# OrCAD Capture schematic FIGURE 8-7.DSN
size A
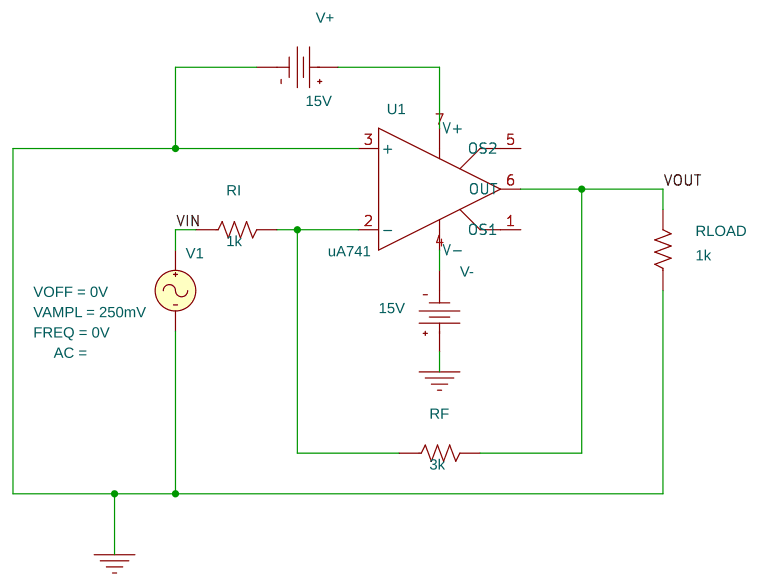
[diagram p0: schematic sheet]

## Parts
RF  3k  [AX/RC05]
RI  1k  [AX/RC05]
RLOAD  1k  [AX/RC05]
U1  uA741  [DIP.100/8/W.300/L.450]
V1  VSIN
V+  VDC
V-  VDC

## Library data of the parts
RF RI RLOAD = R
U1 = uA741
V1 = VSIN: FREQ: 0V; VAMPL: 250mV; VOFF: 0V
V+ V- = VDC: DC: 15V

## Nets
VIN: RI.1 V1.1(+)
0: RLOAD.1 U1.3(+) V1.2(-) V+.1(-) V-.0(+)
VOUT: RF.2 RLOAD.2 U1.6(OUT)
N00374: RF.1 RI.2 U1.2(-)
N00825: U1.4(V-) V-.1(-)
N00837: U1.7(V+) V+.0(+)

Not connected (* = marked no-connect by the designer): U1 1(OS1) 5(OS2)
